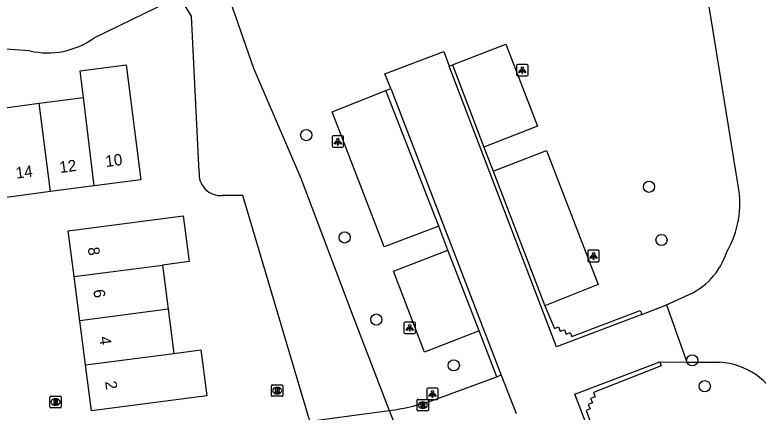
# Model space of a CAD drawing. Extents: x 159451 to 160663, y 388402 to 389723.
# Drawn here: x 159555.6 to 159620.6, y 389258.6 to 389293.3 of the extents above; entities that cross this region are included whole.
import ezdxf

# ---------------------------------------------------------------- set-up
doc = ezdxf.new("R2010")
doc.units = 0
for name, color, linetype in [('IMGEO_Boom', 7, 'Continuous'), ('IMGEO_Lichtpunt', 7, 'Continuous'), ('IMGEO_Meer_plas_ven_vijver', 7, 'Continuous'), ('IMGEO_Pand', 7, 'Continuous'), ('IMGEO_Pand_nummerreeks', 7, 'Continuous'), ('IMGEO_Parkeervlak_halfverhard', 7, 'Continuous'), ('IMGEO_Rijbaan_lokaal_gesloten', 7, 'Continuous'), ('IMGEO_Rijbaan_lokaal_halfverhard', 7, 'Continuous'), ('IMGEO_Rioolput', 7, 'Continuous')]:
    doc.layers.add(name, color=color, linetype=linetype)

msp = doc.modelspace()

# ---------------------------------------------------------------- linework, layer by layer
at = {"layer": 'IMGEO_Boom'}
for centre in [(159581.107, 389282.768), (159611.063, 389278.254), (159584.465, 389273.835), (159612.156, 389273.613), (159587.237, 389266.664), (159614.842, 389263.099), (159594.004, 389262.662), (159615.939, 389260.837)]:
    msp.add_circle(centre, 0.489, dxfattribs=at)
at = {"layer": 'IMGEO_Lichtpunt'}
for p, q in [((159599.495, 389288.843), (159599.495, 389288.036)), ((159599.495, 389288.843), (159599.495, 389288.036)), ((159600.397, 389288.938), (159599.589, 389288.938)), ((159600.397, 389288.938), (159599.589, 389288.938)), ((159600.491, 389288.036), (159600.491, 389288.843)), ((159600.491, 389288.036), (159600.491, 389288.843)), ((159599.589, 389287.942), (159600.397, 389287.942)), ((159599.589, 389287.942), (159600.397, 389287.942)), ((159583.37, 389282.606), (159583.37, 389281.799)), ((159583.37, 389282.606), (159583.37, 389281.799)), ((159584.272, 389282.701), (159583.464, 389282.701)), ((159584.272, 389282.701), (159583.464, 389282.701)), ((159584.366, 389281.799), (159584.366, 389282.606)), ((159584.366, 389281.799), (159584.366, 389282.606)), ((159583.464, 389281.705), (159584.272, 389281.705)), ((159583.464, 389281.705), (159584.272, 389281.705)), ((159605.717, 389272.618), (159605.717, 389271.811)), ((159605.717, 389272.618), (159605.717, 389271.811)), ((159606.619, 389272.713), (159605.811, 389272.713)), ((159606.619, 389272.713), (159605.811, 389272.713)), ((159606.713, 389271.811), (159606.713, 389272.618)), ((159606.713, 389271.811), (159606.713, 389272.618)), ((159605.811, 389271.717), (159606.619, 389271.717)), ((159605.811, 389271.717), (159606.619, 389271.717)), ((159589.649, 389266.341), (159589.649, 389265.534)), ((159589.649, 389266.341), (159589.649, 389265.534)), ((159590.551, 389266.436), (159589.743, 389266.436)), ((159590.551, 389266.436), (159589.743, 389266.436)), ((159590.645, 389265.534), (159590.645, 389266.341)), ((159590.645, 389265.534), (159590.645, 389266.341)), ((159589.743, 389265.44), (159590.551, 389265.44)), ((159589.743, 389265.44), (159590.551, 389265.44)), ((159591.647, 389260.571), (159591.647, 389259.764)), ((159591.647, 389260.571), (159591.647, 389259.764)), ((159592.549, 389260.666), (159591.741, 389260.666)), ((159592.549, 389260.666), (159591.741, 389260.666)), ((159592.643, 389259.764), (159592.643, 389260.571)), ((159592.643, 389259.764), (159592.643, 389260.571)), ((159591.741, 389259.67), (159592.549, 389259.67)), ((159591.741, 389259.67), (159592.549, 389259.67))]:
    msp.add_line(p, q, dxfattribs=at)
for points in [[(159599.869, 389288.507), (159599.908, 389288.479), (159599.72, 389288.217), (159599.682, 389288.244), (159599.869, 389288.507)], [(159599.971, 389288.459), (159600.018, 389288.459), (159600.018, 389288.137), (159599.971, 389288.137), (159599.971, 389288.459)], [(159600.081, 389288.479), (159600.119, 389288.506), (159600.306, 389288.244), (159600.267, 389288.216), (159600.081, 389288.479)], [(159583.744, 389282.27), (159583.783, 389282.242), (159583.595, 389281.98), (159583.557, 389282.007), (159583.744, 389282.27)], [(159583.846, 389282.222), (159583.893, 389282.222), (159583.893, 389281.9), (159583.846, 389281.9), (159583.846, 389282.222)], [(159583.956, 389282.242), (159583.994, 389282.269), (159584.181, 389282.007), (159584.142, 389281.979), (159583.956, 389282.242)], [(159606.091, 389272.282), (159606.13, 389272.254), (159605.942, 389271.992), (159605.904, 389272.019), (159606.091, 389272.282)], [(159606.193, 389272.234), (159606.24, 389272.234), (159606.24, 389271.912), (159606.193, 389271.912), (159606.193, 389272.234)], [(159606.303, 389272.254), (159606.341, 389272.281), (159606.528, 389272.019), (159606.489, 389271.991), (159606.303, 389272.254)], [(159590.023, 389266.005), (159590.062, 389265.977), (159589.874, 389265.715), (159589.836, 389265.742), (159590.023, 389266.005)], [(159590.125, 389265.957), (159590.172, 389265.957), (159590.172, 389265.635), (159590.125, 389265.635), (159590.125, 389265.957)], [(159590.235, 389265.977), (159590.273, 389266.004), (159590.46, 389265.742), (159590.421, 389265.714), (159590.235, 389265.977)], [(159592.021, 389260.235), (159592.06, 389260.207), (159591.872, 389259.945), (159591.834, 389259.972), (159592.021, 389260.235)], [(159592.123, 389260.187), (159592.17, 389260.187), (159592.17, 389259.865), (159592.123, 389259.865), (159592.123, 389260.187)], [(159592.233, 389260.207), (159592.271, 389260.234), (159592.458, 389259.972), (159592.419, 389259.944), (159592.233, 389260.207)]]:
    msp.add_lwpolyline(points, dxfattribs=at)
for centre in [(159599.994, 389288.641), (159583.869, 389282.404), (159606.216, 389272.416), (159590.148, 389266.139), (159592.146, 389260.369)]:
    msp.add_circle(centre, 0.0994, dxfattribs=at)
for centre, start, end in [((159599.589, 389288.843), 90, 180), ((159599.589, 389288.843), 90, 180), ((159600.397, 389288.843), 0, 90), ((159600.397, 389288.843), 0, 90), ((159599.589, 389288.036), 180, 270), ((159599.589, 389288.036), 180, 270), ((159600.397, 389288.036), 270, 0), ((159600.397, 389288.036), 270, 360), ((159583.464, 389282.606), 90, 180), ((159583.464, 389282.606), 90, 180), ((159584.272, 389282.606), 0, 90), ((159584.272, 389282.606), 0, 90), ((159583.464, 389281.799), 180, 270), ((159583.464, 389281.799), 180, 270), ((159584.272, 389281.799), 270, 0), ((159584.272, 389281.799), 270, 360), ((159605.811, 389272.618), 90, 180), ((159605.811, 389272.618), 90, 180), ((159606.619, 389272.618), 0, 90), ((159606.619, 389272.618), 0, 90), ((159605.811, 389271.811), 180, 270), ((159605.811, 389271.811), 180, 270), ((159606.619, 389271.811), 270, 0), ((159606.619, 389271.811), 270, 360), ((159589.743, 389266.341), 90, 180), ((159589.743, 389266.341), 90, 180), ((159590.551, 389266.341), 0, 90), ((159590.551, 389266.341), 0, 90), ((159589.743, 389265.534), 180, 270), ((159589.743, 389265.534), 180, 270), ((159590.551, 389265.534), 270, 0), ((159590.551, 389265.534), 270, 360), ((159591.741, 389260.571), 90, 180), ((159591.741, 389260.571), 90, 180), ((159592.549, 389260.571), 0, 90), ((159592.549, 389260.571), 0, 90), ((159591.741, 389259.764), 180, 270), ((159591.741, 389259.764), 180, 270), ((159592.549, 389259.764), 270, 0), ((159592.549, 389259.764), 270, 360)]:
    msp.add_arc(centre, 0.0946, start, end, dxfattribs=at)
at = {"layer": 'IMGEO_Meer_plas_ven_vijver'}
for points in [[(159574.217, 389295.171), (159576.492, 389288.625), (159580.643, 389278.999), (159585.177, 389266.997), (159588.35, 389258.709)], [(159571.755, 389279.564), (159571.085, 389293.162), (159570.386, 389294.298), (159569.066, 389294.418), (159562.535, 389291.222)], [(159556.966, 389290.126), (159546.129, 389290.863), (159532.239, 389289.197)], [(159581.411, 389257.784), (159575.559, 389277.502), (159573.786, 389277.496)]]:
    msp.add_lwpolyline(points, dxfattribs=at)
for centre, radius, start, end in [((159558.519, 389296.933), 6.981, 257.14877, 305.1187), ((159573.634, 389279.378), 1.888, 174.357, 274.60866)]:
    msp.add_arc(centre, radius, start, end, dxfattribs=at)
at = {"layer": 'IMGEO_Pand'}
for points in [[(159561.639, 389286.044), (159561.351, 389288.395), (159565.365, 389288.906), (159566.652, 389278.858), (159562.584, 389278.33)], [(159557.776, 389285.546), (159561.639, 389286.044)], [(159562.584, 389278.33), (159561.639, 389286.044)], [(159553.913, 389285.047), (159557.776, 389285.546)], [(159558.771, 389277.834), (159557.776, 389285.546)], [(159558.771, 389277.834), (159554.906, 389277.332)], [(159562.584, 389278.33), (159558.771, 389277.834)], [(159560.83, 389270.413), (159560.311, 389274.413), (159570.362, 389275.731), (159570.891, 389271.725), (159568.539, 389271.414)], [(159560.83, 389270.413), (159568.539, 389271.414)], [(159568.539, 389271.414), (159569.046, 389267.555)], [(159561.332, 389266.553), (159560.83, 389270.413)], [(159569.046, 389267.555), (159561.332, 389266.553)], [(159569.046, 389267.555), (159569.552, 389263.705)], [(159561.831, 389262.703), (159561.332, 389266.553)], [(159569.552, 389263.705), (159571.892, 389264.011), (159572.415, 389260.004), (159562.352, 389258.693), (159561.831, 389262.703)], [(159561.831, 389262.703), (159569.552, 389263.705)]]:
    msp.add_lwpolyline(points, dxfattribs=at)
at = {"layer": 'IMGEO_Parkeervlak_halfverhard'}
for points in [[(159593.899, 389288.918), (159598.538, 389290.709), (159601.305, 389283.56), (159596.641, 389281.714)], [(159592.686, 389274.813), (159587.925, 389273.015), (159583.387, 389284.803), (159588.068, 389286.657)], [(159597.434, 389279.629), (159602.098, 389281.418), (159606.635, 389269.713), (159601.97, 389267.871)], [(159596.212, 389265.672), (159591.455, 389263.814), (159588.734, 389270.886), (159593.496, 389272.735)]]:
    msp.add_lwpolyline(points, dxfattribs=at)
at = {"layer": 'IMGEO_Rijbaan_lokaal_gesloten'}
for points in [[(159618.859, 389278.354), (159615.655, 389298.149)], [(159588.496, 389286.827), (159587.984, 389288.121), (159593.138, 389290.059), (159593.594, 389288.8)], [(159610.45, 389267.112), (159602.979, 389264.271), (159593.594, 389288.8)], [(159588.496, 389286.827), (159598.147, 389261.804)], [(159612.605, 389267.948), (159614.256, 389268.699)], [(159610.45, 389267.112), (159612.529, 389267.914), (159612.605, 389267.948)], [(159612.605, 389267.948), (159614.38, 389262.934)], [(159614.564, 389234.245), (159611.719, 389241.556), (159604.568, 389260.14), (159612.01, 389262.967)], [(159612.01, 389262.967), (159614.38, 389262.934)], [(159614.38, 389262.934), (159617.251, 389262.935)], [(159592.53, 389259.74), (159597.779, 389261.674)], [(159598.147, 389261.804), (159597.779, 389261.674)], [(159598.147, 389261.804), (159599.457, 389258.469)], [(159581.411, 389257.784), (159588.35, 389258.709)], [(159588.35, 389258.709), (159589.73, 389255.325)]]:
    msp.add_lwpolyline(points, dxfattribs=at)
for centre, radius, start, end in [((159610.578, 389276.803), 8.425, 329.81877, 10.61177), ((159611.898, 389274.511), 6.272, 292.08596, 341.94524), ((159616.857, 389256.687), 6.26, 24.93997, 86.38805), ((159585.713, 389278.389), 19.855, 277.63152, 290.07946)]:
    msp.add_arc(centre, radius, start, end, dxfattribs=at)
at = {"layer": 'IMGEO_Rijbaan_lokaal_halfverhard'}
for points in [[(159593.594, 389288.8), (159593.899, 389288.918)], [(159593.899, 389288.918), (159596.641, 389281.714)], [(159588.068, 389286.657), (159588.496, 389286.827)], [(159592.686, 389274.813), (159588.068, 389286.657)], [(159596.641, 389281.714), (159597.434, 389279.629)], [(159597.434, 389279.629), (159601.97, 389267.871)], [(159593.496, 389272.735), (159592.686, 389274.813)], [(159596.212, 389265.672), (159593.496, 389272.735)], [(159601.97, 389267.871), (159602.795, 389265.891), (159603.146, 389266.023), (159603.302, 389265.646), (159603.676, 389265.776), (159603.812, 389265.4), (159604.182, 389265.546), (159604.329, 389265.174), (159610.291, 389267.455), (159610.45, 389267.112)], [(159597.779, 389261.674), (159596.212, 389265.672)], [(159612.01, 389262.967), (159612.12, 389262.61), (159606.206, 389260.293), (159606.356, 389259.915), (159605.961, 389259.776), (159606.13, 389259.404), (159605.745, 389259.256), (159605.912, 389258.88), (159605.561, 389258.716), (159606.554, 389256.085)]]:
    msp.add_lwpolyline(points, dxfattribs=at)
at = {"layer": 'IMGEO_Rioolput'}
for p, q in [((159578.141, 389260.959), (159578.993, 389260.959)), ((159578.066, 389260.033), (159578.066, 389260.885)), ((159578.554, 389260.739), (159578.579, 389260.739)), ((159579.067, 389260.885), (159579.067, 389260.033)), ((159558.705, 389259.033), (159558.705, 389259.885)), ((159558.78, 389259.959), (159559.632, 389259.959)), ((159559.193, 389259.739), (159559.218, 389259.739)), ((159559.706, 389259.885), (159559.706, 389259.033)), ((159578.993, 389259.959), (159578.141, 389259.959)), ((159578.577, 389260.179), (159578.552, 389260.179)), ((159590.795, 389258.763), (159590.795, 389259.615)), ((159590.87, 389259.689), (159591.722, 389259.689)), ((159591.796, 389259.615), (159591.796, 389258.763)), ((159559.632, 389258.959), (159558.78, 389258.959)), ((159559.216, 389259.179), (159559.191, 389259.179)), ((159591.283, 389259.469), (159591.308, 389259.469)), ((159591.722, 389258.689), (159590.87, 389258.689)), ((159591.306, 389258.909), (159591.281, 389258.909))]:
    msp.add_line(p, q, dxfattribs=at)
for points in [[(159578.141, 389260.959), (159578.993, 389260.959)], [(159578.066, 389260.033), (159578.066, 389260.885)], [(159578.655, 389260.657), (159578.403, 389260.659), (159578.403, 389260.259)], [(159578.403, 389260.259), (159578.527, 389260.259), (159578.527, 389260.421), (159578.538, 389260.421)], [(159578.581, 389260.578), (159578.527, 389260.578), (159578.527, 389260.497)], [(159578.527, 389260.497), (159578.579, 389260.497)], [(159578.585, 389260.392), (159578.656, 389260.259), (159578.796, 389260.259), (159578.731, 389260.385)], [(159579.067, 389260.885), (159579.067, 389260.033)], [(159558.705, 389259.033), (159558.705, 389259.885)], [(159558.78, 389259.959), (159559.632, 389259.959)], [(159559.294, 389259.657), (159559.042, 389259.659), (159559.042, 389259.259)], [(159559.706, 389259.885), (159559.706, 389259.033)], [(159578.993, 389259.959), (159578.141, 389259.959)], [(159590.795, 389258.763), (159590.795, 389259.615)], [(159590.87, 389259.689), (159591.722, 389259.689)], [(159591.796, 389259.615), (159591.796, 389258.763)], [(159559.632, 389258.959), (159558.78, 389258.959)], [(159559.042, 389259.259), (159559.166, 389259.259), (159559.166, 389259.421), (159559.177, 389259.421)], [(159559.22, 389259.578), (159559.166, 389259.578), (159559.166, 389259.497)], [(159559.166, 389259.497), (159559.218, 389259.497)], [(159559.224, 389259.392), (159559.295, 389259.259), (159559.435, 389259.259), (159559.37, 389259.385)], [(159591.384, 389259.387), (159591.132, 389259.389), (159591.132, 389258.989)], [(159591.132, 389258.989), (159591.256, 389258.989), (159591.256, 389259.151), (159591.267, 389259.151)], [(159591.31, 389259.308), (159591.256, 389259.308), (159591.256, 389259.227)], [(159591.256, 389259.227), (159591.308, 389259.227)], [(159591.314, 389259.122), (159591.385, 389258.989), (159591.525, 389258.989), (159591.46, 389259.115)], [(159591.722, 389258.689), (159590.87, 389258.689)]]:
    msp.add_lwpolyline(points, dxfattribs=at)
for centre, radius, start, end in [((159578.143, 389260.883), 0.0765, 91.55205, 178.44795), ((159578.143, 389260.883), 0.0765, 91.55205, 178.44795), ((159578.991, 389260.883), 0.0765, 1.55205, 88.44795), ((159578.991, 389260.883), 0.0765, 1.55205, 88.44795), ((159578.537, 389260.368), 0.0533, 26.02933, 88.69889), ((159578.563, 389260.686), 0.19, 274.7715, 282.96867), ((159578.587, 389260.482), 0.0964, 77.00612, 93.18647), ((159578.601, 389260.539), 0.0378, 276.66336, 79.67722), ((159578.654, 389260.547), 0.109, 350.36119, 89.41601), ((159578.652, 389260.547), 0.112, 277.58423, 350.98172), ((159578.636, 389260.332), 0.108, 29.51342, 73.79051), ((159558.782, 389259.883), 0.0765, 91.55205, 178.44795), ((159558.782, 389259.883), 0.0765, 91.55205, 178.44795), ((159559.293, 389259.547), 0.109, 350.36119, 89.41601), ((159559.63, 389259.883), 0.0765, 1.55205, 88.44795), ((159559.63, 389259.883), 0.0765, 1.55205, 88.44795), ((159578.143, 389260.035), 0.0765, 181.55205, 268.44795), ((159578.143, 389260.035), 0.0765, 181.55205, 268.44795), ((159578.991, 389260.035), 0.0765, 271.55205, 358.44795), ((159578.991, 389260.035), 0.0765, 271.55205, 358.44795), ((159590.872, 389259.613), 0.0765, 91.55205, 178.44795), ((159590.872, 389259.613), 0.0765, 91.55205, 178.44795), ((159591.72, 389259.613), 0.0765, 1.55205, 88.44795), ((159591.72, 389259.613), 0.0765, 1.55205, 88.44795), ((159558.782, 389259.035), 0.0765, 181.55205, 268.44795), ((159558.782, 389259.035), 0.0765, 181.55205, 268.44795), ((159559.176, 389259.368), 0.0533, 26.02933, 88.69889), ((159559.202, 389259.686), 0.19, 274.7715, 282.96867), ((159559.226, 389259.482), 0.0964, 77.00612, 93.18647), ((159559.24, 389259.539), 0.0378, 276.66336, 79.67722), ((159559.291, 389259.547), 0.112, 277.58423, 350.98172), ((159559.275, 389259.332), 0.108, 29.51342, 73.79051), ((159559.63, 389259.035), 0.0765, 271.55205, 358.44795), ((159559.63, 389259.035), 0.0765, 271.55205, 358.44795), ((159591.266, 389259.098), 0.0533, 26.02933, 88.69889), ((159591.292, 389259.416), 0.19, 274.7715, 282.96867), ((159591.316, 389259.212), 0.0964, 77.00612, 93.18647), ((159591.33, 389259.269), 0.0378, 276.66336, 79.67722), ((159591.383, 389259.277), 0.109, 350.36119, 89.41601), ((159591.381, 389259.277), 0.112, 277.58423, 350.98172), ((159591.365, 389259.062), 0.108, 29.51342, 73.79051), ((159590.872, 389258.765), 0.0765, 181.55205, 268.44795), ((159590.872, 389258.765), 0.0765, 181.55205, 268.44795), ((159591.72, 389258.765), 0.0765, 271.55205, 358.44795), ((159591.72, 389258.765), 0.0765, 271.55205, 358.44795)]:
    msp.add_arc(centre, radius, start, end, dxfattribs=at)
for centre, major_axis, ratio, start_param, end_param in [((159578.553, 389260.459), (-0.387, 0.002), 0.722429, 4.712389, 7.853982), ((159578.578, 389260.459), (-0.39, 0.002), 0.717154, 1.570796, 4.712389), ((159559.192, 389259.459), (-0.387, 0.002), 0.722429, 4.712389, 7.853982), ((159559.217, 389259.459), (-0.39, 0.002), 0.717154, 1.570796, 4.712389), ((159591.282, 389259.189), (-0.387, 0.002), 0.722429, 4.712389, 7.853982), ((159591.307, 389259.189), (-0.39, 0.002), 0.717154, 1.570796, 4.712389)]:
    msp.add_ellipse(centre, major_axis=major_axis, ratio=ratio, start_param=start_param, end_param=end_param, dxfattribs=at)

# ---------------------------------------------------------------- texts
at = {"layer": 'IMGEO_Pand_nummerreeks'}
for s, rotation, p in [('10', 7.40261, (159563.621, 389279.977)), ('12', 7.40261, (159559.603, 389279.455)), ('14', 7.40261, (159555.784, 389278.959)), ('8', 277.39667, (159562.015, 389272.937)), ('6', 277.39667, (159562.495, 389269.241)), ('4', 277.39667, (159563.028, 389265.132)), ('2', 277.39667, (159563.533, 389261.242))]:
    msp.add_text(s, height=1, rotation=rotation, dxfattribs=at).set_placement(p)

doc.saveas('drawing.dxf')
